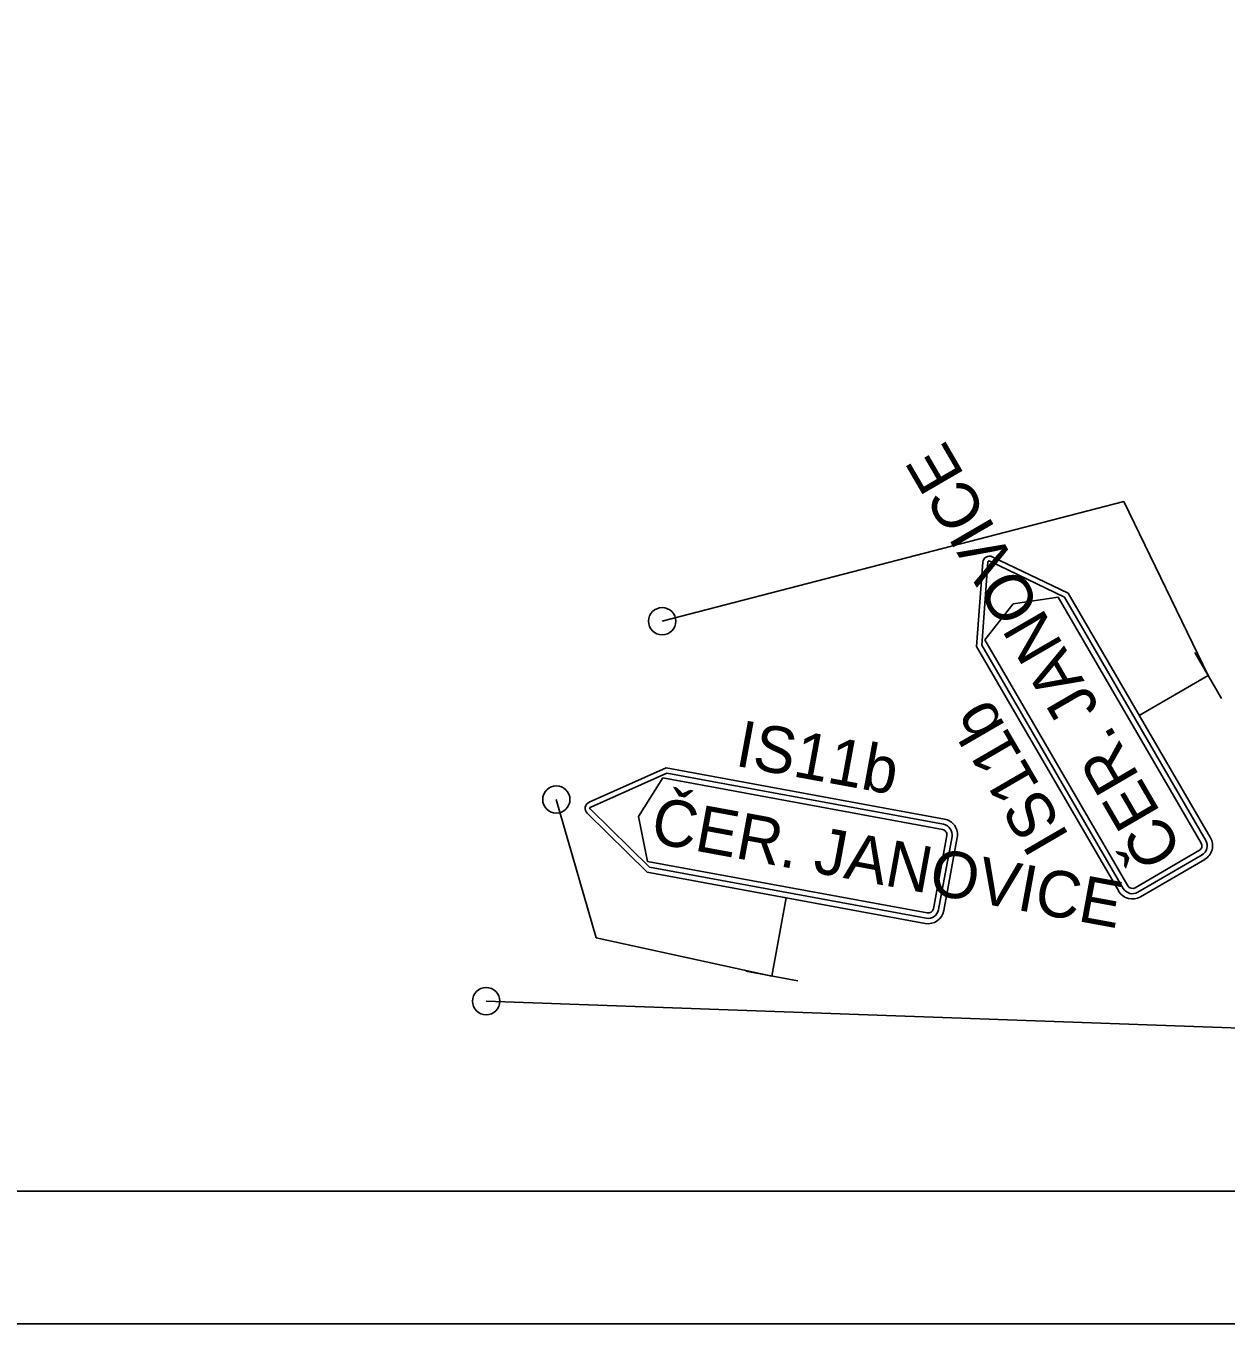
# Model space of a CAD drawing. Extents: x -688893 to -679983, y -1088371 to -1075771.
# Drawn here: x -687100 to -685743, y -1088371 to -1086903 of the extents above; entities that cross this region are included whole.
import ezdxf

# ---------------------------------------------------------------- set-up
doc = ezdxf.new("R2010")
doc.units = 0
for name, color, linetype in [('ramecek', 7, 'Continuous'), ('SDZ', 7, 'Continuous'), ('SDZ ozn', 7, 'Continuous'), ('SDZ plochy', 7, 'Continuous'), ('SDZ symbol', 7, 'Continuous')]:
    doc.layers.add(name, color=color, linetype=linetype)

msp = doc.modelspace()

# ---------------------------------------------------------------- linework, layer by layer
at = {"layer": 'ramecek'}
for points in [[(-679983.4, -1075770.7), (-679983.4, -1088370.7), (-688893.4, -1088370.7), (-688893.4, -1075770.7)], [(-680133.4, -1076070.7), (-680133.4, -1088220.7), (-688743.4, -1088220.7), (-688743.4, -1076070.7)]]:
    msp.add_lwpolyline(points, close=True, dxfattribs=at)
at = {"layer": 'SDZ'}
for p, q in [((-686024.9, -1087604.9), (-686017.8, -1087509.6)), ((-686012.1, -1087509.5), (-686018.8, -1087603.4)), ((-686017.8, -1087509.8), (-686017.8, -1087509.8)), ((-685925.5, -1087549.1), (-686009.9, -1087508.3)), ((-686007, -1087503.4), (-685921.2, -1087544.6)), ((-685983.6, -1087556.6), (-685932.5, -1087549)), ((-685932.5, -1087549), (-685770.8, -1087827)), ((-685765.6, -1087824), (-685925.5, -1087549.1)), ((-685921.2, -1087544.6), (-685760.4, -1087821)), ((-686015.5, -1087597.3), (-685983.6, -1087556.6)), ((-685853.8, -1087875.3), (-686015.5, -1087597.3)), ((-685864.1, -1087881.3), (-686024.9, -1087604.9)), ((-686018.8, -1087603.4), (-685858.9, -1087878.3)), ((-685747.9, -1087663.5), (-685778.1, -1087611.6)), ((-685840.8, -1087682.8), (-685763, -1087637.5)), ((-686375.7, -1087742), (-686462.9, -1087781)), ((-686061.2, -1087799.9), (-686375.7, -1087742)), ((-686461.1, -1087786.3), (-686375, -1087748.2)), ((-686379.6, -1087753.5), (-686407.2, -1087797.2)), ((-686063.3, -1087811.7), (-686379.6, -1087753.5)), ((-686375, -1087748.2), (-686062.2, -1087805.8)), ((-686462.8, -1087780.9), (-686462.8, -1087780.9)), ((-686394.5, -1087854.4), (-686461.5, -1087788.8)), ((-686465.2, -1087793.2), (-686397.4, -1087860)), ((-686407.2, -1087797.2), (-686397, -1087847.9)), ((-686073.7, -1087901.3), (-686058.5, -1087818.6)), ((-686052.6, -1087819.7), (-686067.8, -1087902.3)), ((-686061.9, -1087903.4), (-686046.7, -1087820.8)), ((-686397, -1087847.9), (-686080.7, -1087906.1)), ((-685772.9, -1087835.2), (-685845.6, -1087877.5)), ((-685842.5, -1087882.7), (-685769.9, -1087840.4)), ((-685766.9, -1087845.6), (-685839.5, -1087887.8)), ((-686397.4, -1087860), (-686082.9, -1087917.9)), ((-686081.8, -1087912), (-686394.5, -1087854.4)), ((-686240.1, -1087889), (-686256.4, -1087977.5)), ((-686226.9, -1087982.9), (-686285.9, -1087972))]:
    msp.add_line(p, q, dxfattribs=at)
for points in [[(-686380.3, -1087576.3), (-685858.4, -1087441), (-685763, -1087637.5)], [(-686500, -1087777.8), (-686454.9, -1087934.1), (-686256.4, -1087977.5)], [(-686579.3, -1088005.8), (-685600.1, -1088040.9)]]:
    msp.add_lwpolyline(points, dxfattribs=at)
for centre in [(-686380.3, -1087576.3), (-686500, -1087777.8), (-686579.3, -1088005.8)]:
    msp.add_circle(centre, 15.4, dxfattribs=at)
for centre, radius, start, end in [((-686010.3, -1087510.2), 7.5, 64.3772, 175.6955), ((-686010.6, -1087509.6), 1.5, 64.1819, 175.8848), ((-686459.9, -1087787.8), 7.5, 114.0674, 225.3857), ((-686460.5, -1087787.7), 1.5, 113.8781, 225.581), ((-686064.4, -1087817.6), 18, 349.5775, 79.5775), ((-686064.4, -1087817.6), 6, 349.5775, 79.5775), ((-686064.4, -1087817.6), 12, 349.5775, 79.5775), ((-685776, -1087830.1), 6, 300.1855, 30.1855), ((-685776, -1087830.1), 12, 300.1855, 30.1855), ((-685776, -1087830.1), 18, 300.1855, 30.1855), ((-685848.6, -1087872.3), 12, 210.1855, 300.1855), ((-685848.6, -1087872.3), 6, 210.1855, 300.1855), ((-685848.6, -1087872.3), 18, 210.1855, 300.1855), ((-686079.6, -1087900.2), 18, 259.5775, 349.5775), ((-686079.6, -1087900.2), 12, 259.5775, 349.5775), ((-686079.6, -1087900.2), 6, 259.5775, 349.5775)]:
    msp.add_arc(centre, radius, start, end, dxfattribs=at)
at = {"layer": 'SDZ plochy'}
for p, q in [((-686017.8, -1087509.6), (-686024.9, -1087604.9)), ((-686018.8, -1087603.4), (-686012.1, -1087509.5)), ((-686012.1, -1087509.5), (-686018.8, -1087603.4)), ((-686009.9, -1087508.3), (-685925.5, -1087549.1)), ((-685925.5, -1087549.1), (-686009.9, -1087508.3)), ((-685921.2, -1087544.6), (-686007, -1087503.4)), ((-685932.5, -1087549), (-685983.6, -1087556.6)), ((-685983.6, -1087556.6), (-685932.5, -1087549)), ((-685770.8, -1087827), (-685932.5, -1087549)), ((-685932.5, -1087549), (-685770.8, -1087827)), ((-685925.5, -1087549.1), (-685765.6, -1087824)), ((-685765.6, -1087824), (-685925.5, -1087549.1)), ((-685760.4, -1087821), (-685921.2, -1087544.6)), ((-685983.6, -1087556.6), (-686015.5, -1087597.3)), ((-686015.5, -1087597.3), (-685983.6, -1087556.6)), ((-686015.5, -1087597.3), (-685853.8, -1087875.3)), ((-685853.8, -1087875.3), (-686015.5, -1087597.3)), ((-686024.9, -1087604.9), (-685864.1, -1087881.3)), ((-685858.9, -1087878.3), (-686018.8, -1087603.4)), ((-686018.8, -1087603.4), (-685858.9, -1087878.3)), ((-686375.7, -1087742), (-686462.9, -1087781)), ((-686061.2, -1087799.9), (-686375.7, -1087742)), ((-686461.1, -1087786.3), (-686375, -1087748.2)), ((-686375, -1087748.2), (-686461.1, -1087786.3)), ((-686379.6, -1087753.5), (-686407.2, -1087797.2)), ((-686407.2, -1087797.2), (-686379.6, -1087753.5)), ((-686063.3, -1087811.7), (-686379.6, -1087753.5)), ((-686379.6, -1087753.5), (-686063.3, -1087811.7)), ((-686375, -1087748.2), (-686062.2, -1087805.8)), ((-686062.2, -1087805.8), (-686375, -1087748.2)), ((-686394.5, -1087854.4), (-686461.5, -1087788.8)), ((-686461.5, -1087788.8), (-686394.5, -1087854.4)), ((-686465.2, -1087793.2), (-686397.4, -1087860)), ((-686407.2, -1087797.2), (-686397, -1087847.9)), ((-686397, -1087847.9), (-686407.2, -1087797.2)), ((-686073.7, -1087901.3), (-686058.5, -1087818.6)), ((-686058.5, -1087818.6), (-686073.7, -1087901.3)), ((-686052.6, -1087819.7), (-686067.8, -1087902.3)), ((-686067.8, -1087902.3), (-686052.6, -1087819.7)), ((-686061.9, -1087903.4), (-686046.7, -1087820.8)), ((-686397, -1087847.9), (-686080.7, -1087906.1)), ((-686080.7, -1087906.1), (-686397, -1087847.9)), ((-685845.6, -1087877.5), (-685772.9, -1087835.2)), ((-685772.9, -1087835.2), (-685845.6, -1087877.5)), ((-685769.9, -1087840.4), (-685842.5, -1087882.7)), ((-685842.5, -1087882.7), (-685769.9, -1087840.4)), ((-685839.5, -1087887.8), (-685766.9, -1087845.6)), ((-686397.4, -1087860), (-686082.9, -1087917.9)), ((-686081.8, -1087912), (-686394.5, -1087854.4)), ((-686394.5, -1087854.4), (-686081.8, -1087912))]:
    msp.add_line(p, q, dxfattribs=at)
for centre, radius, start, end in [((-686010.3, -1087510.2), 7.5, 64.3772, 175.6955), ((-686010.6, -1087509.6), 1.5, 64.1819, 175.8848), ((-686010.6, -1087509.6), 1.5, 64.1819, 175.8848), ((-686459.9, -1087787.8), 7.5, 114.0674, 225.3857), ((-686460.5, -1087787.7), 1.5, 113.8781, 225.581), ((-686460.5, -1087787.7), 1.5, 113.8781, 225.581), ((-686064.4, -1087817.6), 18, 349.5775, 79.5775), ((-686064.4, -1087817.6), 6, 349.5775, 79.5775), ((-686064.4, -1087817.6), 6, 349.5775, 79.5775), ((-686064.4, -1087817.6), 12, 349.5775, 79.5775), ((-686064.4, -1087817.6), 12, 349.5775, 79.5775), ((-685776, -1087830.1), 6, 300.1855, 30.1855), ((-685776, -1087830.1), 6, 300.1855, 30.1855), ((-685776, -1087830.1), 12, 300.1855, 30.1855), ((-685776, -1087830.1), 12, 300.1855, 30.1855), ((-685776, -1087830.1), 18, 300.1855, 30.1855), ((-685848.6, -1087872.3), 12, 210.1855, 300.1855), ((-685848.6, -1087872.3), 12, 210.1855, 300.1855), ((-685848.6, -1087872.3), 6, 210.1855, 300.1855), ((-685848.6, -1087872.3), 6, 210.1855, 300.1855), ((-685848.6, -1087872.3), 18, 210.1855, 300.1855), ((-686079.6, -1087900.2), 18, 259.5775, 349.5775), ((-686079.6, -1087900.2), 12, 259.5775, 349.5775), ((-686079.6, -1087900.2), 12, 259.5775, 349.5775), ((-686079.6, -1087900.2), 6, 259.5775, 349.5775), ((-686079.6, -1087900.2), 6, 259.5775, 349.5775)]:
    msp.add_arc(centre, radius, start, end, dxfattribs=at)

# ---------------------------------------------------------------- texts
at = {"layer": 'SDZ ozn'}
for rotation, p in [(120.1855, (-685919, -1087819.8)), (349.5775, (-686299.2, -1087739.4))]:
    msp.add_text('IS11b', height=52.5, rotation=rotation, dxfattribs=at).set_placement(p)
at = {"layer": 'SDZ symbol'}
for rotation, p in [(120.1855, (-685790.7, -1087836.1)), (349.5775, (-686395.1, -1087826.1))]:
    msp.add_text('ČER. JANOVICE', height=52.5, rotation=rotation, dxfattribs=at).set_placement(p)

doc.saveas('drawing.dxf')
